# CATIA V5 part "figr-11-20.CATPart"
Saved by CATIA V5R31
Part number: Part5
Bounding box of the stored display mesh (mm): x -70 to 70, y -150 to 0, z -1.939 to 20.996
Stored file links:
  D:\PROJECTS\Project 2021\US EDITION\CATIA V5 6R 2021\Resources\Part Files\c11_catia_v5_6r2021_prt\figr-11-20.CATPart
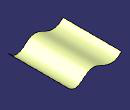
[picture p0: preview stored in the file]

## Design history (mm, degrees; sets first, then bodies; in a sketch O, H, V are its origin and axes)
Body1 (main body)
  Sketch1 on zx-plane, origin (0, 0, 0), H (-1, 0, 0), V (0, 0, 1)
    spline S1 through (-70, 10) (-40, 0) (-10, 20) (30, 10) (70, 20)
  Extrude1: Element1 Sketch1, Lim1 150, Lim2 0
